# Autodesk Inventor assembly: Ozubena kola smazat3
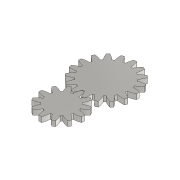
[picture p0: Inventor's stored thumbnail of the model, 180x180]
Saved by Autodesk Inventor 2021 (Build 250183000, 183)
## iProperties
Created: 2024-11
Part Number: Ozubena kola smazat3
Document SubType Name: Assembly
Designer: tatulinek
Author: tatulinek
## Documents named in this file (2)
- C:\Users\tatulinek\Documents\____Zviratka\Ozubena kola smazat3.iam
- C:\Users\tatulinek\Documents\____Zviratka\Ozubena kola smazat3\Design Accelerator\Čelní ozubená kola1.iam
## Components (1 placed, 1 different names)
1. Čelní ozubená kola:1 [sub-assembly]
